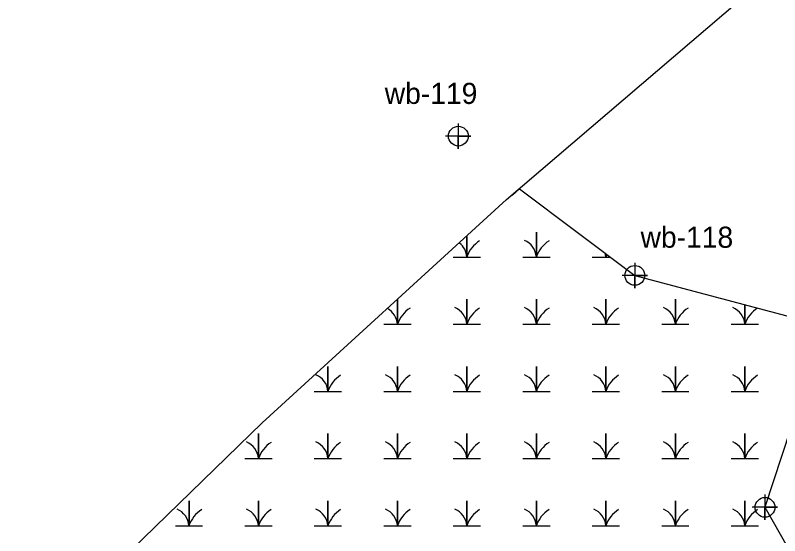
# Model space of a CAD drawing. Extents: x 2379288 to 2381905, y 330670 to 333511.
# Drawn here: x 2380487.2 to 2380668.2, y 332788.3 to 332911.6 of the extents above; entities that cross this region are included whole.
import ezdxf

# ---------------------------------------------------------------- set-up
doc = ezdxf.new("R2010")
doc.units = 0
for name, color, linetype in [('Default', 7, 'Continuous'), ('Exist Environmental Wetland Boundary', 7, 'Continuous'), ('Exist Environmental Wetland Boundary Cogo Number', 7, 'Continuous'), ('Exist Environmental Wetland Boundary Cogo Point CELL', 7, 'Continuous'), ('Exist Hydro Swamp or Marsh', 7, 'Continuous')]:
    doc.layers.add(name, color=color, linetype=linetype)

msp = doc.modelspace()

# ---------------------------------------------------------------- linework, layer by layer
at = {"layer": 'Default'}
msp.add_lwpolyline([(2379288.07, 330873.37), (2380109.3, 332268.58), (2380147.86, 332331.82), (2380190.73, 332397.51), (2380235.65, 332461.81), (2380282.57, 332524.66), (2380331.46, 332586), (2380382.25, 332645.77), (2380434.91, 332703.9), (2380489.37, 332760.35), (2380545.59, 332815.05), (2380603.5, 332867.95), (2380663.06, 332918.99), (2380724.19, 332968.13), (2380786.85, 333015.32), (2380850.96, 333060.51), (2380916.47, 333103.65)], dxfattribs=at)
at = {"layer": 'Exist Environmental Wetland Boundary'}
msp.add_lwpolyline([(2380604.8, 332868.97), (2380606.54, 332870.55), (2380633.85, 332850.01), (2380678.79, 332838.07), (2380664.67, 332795.06), (2380686.7, 332756.16), (2380626.94, 332703.59), (2380578.61, 332658.53)], dxfattribs=at)
at = {"layer": 'Exist Environmental Wetland Boundary Cogo Point CELL'}
for points in [[(2380592.06, 332886), (2380592.06, 332880), (2380592.06, 332883), (2380595.06, 332883), (2380589.06, 332883)], [(2380633.85, 332853.01), (2380633.85, 332847.01), (2380633.85, 332850.01), (2380636.85, 332850.01), (2380630.85, 332850.01)], [(2380664.67, 332798.06), (2380664.67, 332792.06), (2380664.67, 332795.06), (2380667.67, 332795.06), (2380661.67, 332795.06)]]:
    msp.add_lwpolyline(points, dxfattribs=at)
for centre in [(2380592.06, 332883), (2380633.85, 332850.01), (2380664.67, 332795.06)]:
    msp.add_circle(centre, 2.34, dxfattribs=at)
at = {"layer": 'Exist Hydro Swamp or Marsh'}
for points in [[(2380607.32, 332854.36), (2380610.54, 332854.36), (2380610.54, 332860.28), (2380610.54, 332854.36), (2380613.77, 332854.36)], [(2380590.87, 332854.36), (2380594.09, 332854.36), (2380594.09, 332859.24)], [(2380594.09, 332859.24), (2380594.09, 332854.36), (2380597.32, 332854.36)], [(2380623.77, 332854.36), (2380626.99, 332854.36), (2380626.99, 332855.16)], [(2380626.99, 332855.16), (2380626.99, 332854.36), (2380628.06, 332854.36)], [(2380574.42, 332838.45), (2380577.64, 332838.45), (2380577.64, 332844.3)], [(2380577.64, 332844.3), (2380577.64, 332838.45), (2380580.87, 332838.45)], [(2380590.87, 332838.45), (2380594.09, 332838.45), (2380594.09, 332844.36), (2380594.09, 332838.45), (2380597.32, 332838.45)], [(2380607.32, 332838.45), (2380610.54, 332838.45), (2380610.54, 332844.36), (2380610.54, 332838.45), (2380613.77, 332838.45)], [(2380623.77, 332838.45), (2380626.99, 332838.45), (2380626.99, 332844.36), (2380626.99, 332838.45), (2380630.22, 332838.45)], [(2380640.22, 332838.45), (2380643.45, 332838.45), (2380643.45, 332844.36), (2380643.45, 332838.45), (2380646.67, 332838.45)], [(2380656.67, 332838.45), (2380659.9, 332838.45), (2380659.9, 332843.09)], [(2380659.9, 332843.09), (2380659.9, 332838.45), (2380663.12, 332838.45)], [(2380557.96, 332822.53), (2380561.19, 332822.53), (2380561.19, 332828.45), (2380561.19, 332822.53), (2380564.42, 332822.53)], [(2380574.42, 332822.53), (2380577.64, 332822.53), (2380577.64, 332828.45), (2380577.64, 332822.53), (2380580.87, 332822.53)], [(2380590.87, 332822.53), (2380594.09, 332822.53), (2380594.09, 332828.45), (2380594.09, 332822.53), (2380597.32, 332822.53)], [(2380607.32, 332822.53), (2380610.54, 332822.53), (2380610.54, 332828.45), (2380610.54, 332822.53), (2380613.77, 332822.53)], [(2380623.77, 332822.53), (2380626.99, 332822.53), (2380626.99, 332828.45), (2380626.99, 332822.53), (2380630.22, 332822.53)], [(2380640.22, 332822.53), (2380643.45, 332822.53), (2380643.45, 332828.45), (2380643.45, 332822.53), (2380646.67, 332822.53)], [(2380656.67, 332822.53), (2380659.9, 332822.53), (2380659.9, 332828.45), (2380659.9, 332822.53), (2380663.12, 332822.53)], [(2380541.51, 332806.61), (2380544.74, 332806.61), (2380544.74, 332812.53), (2380544.74, 332806.61), (2380547.96, 332806.61)], [(2380557.96, 332806.61), (2380561.19, 332806.61), (2380561.19, 332812.53), (2380561.19, 332806.61), (2380564.42, 332806.61)], [(2380574.42, 332806.61), (2380577.64, 332806.61), (2380577.64, 332812.53), (2380577.64, 332806.61), (2380580.87, 332806.61)], [(2380590.87, 332806.61), (2380594.09, 332806.61), (2380594.09, 332812.53), (2380594.09, 332806.61), (2380597.32, 332806.61)], [(2380607.32, 332806.61), (2380610.54, 332806.61), (2380610.54, 332812.53), (2380610.54, 332806.61), (2380613.77, 332806.61)], [(2380623.77, 332806.61), (2380626.99, 332806.61), (2380626.99, 332812.53), (2380626.99, 332806.61), (2380630.22, 332806.61)], [(2380640.22, 332806.61), (2380643.45, 332806.61), (2380643.45, 332812.53), (2380643.45, 332806.61), (2380646.67, 332806.61)], [(2380656.67, 332806.61), (2380659.9, 332806.61), (2380659.9, 332812.53), (2380659.9, 332806.61), (2380663.12, 332806.61)], [(2380525.06, 332790.69), (2380528.29, 332790.69), (2380528.29, 332796.61), (2380528.29, 332790.69), (2380531.51, 332790.69)], [(2380541.51, 332790.69), (2380544.74, 332790.69), (2380544.74, 332796.61), (2380544.74, 332790.69), (2380547.96, 332790.69)], [(2380557.96, 332790.69), (2380561.19, 332790.69), (2380561.19, 332796.61), (2380561.19, 332790.69), (2380564.42, 332790.69)], [(2380574.42, 332790.69), (2380577.64, 332790.69), (2380577.64, 332796.61), (2380577.64, 332790.69), (2380580.87, 332790.69)], [(2380590.87, 332790.69), (2380594.09, 332790.69), (2380594.09, 332796.61), (2380594.09, 332790.69), (2380597.32, 332790.69)], [(2380607.32, 332790.69), (2380610.54, 332790.69), (2380610.54, 332796.61), (2380610.54, 332790.69), (2380613.77, 332790.69)], [(2380623.77, 332790.69), (2380626.99, 332790.69), (2380626.99, 332796.61), (2380626.99, 332790.69), (2380630.22, 332790.69)], [(2380640.22, 332790.69), (2380643.45, 332790.69), (2380643.45, 332796.61), (2380643.45, 332790.69), (2380646.67, 332790.69)], [(2380656.67, 332790.69), (2380659.9, 332790.69), (2380659.9, 332796.61), (2380659.9, 332790.69), (2380663.12, 332790.69)]]:
    msp.add_lwpolyline(points, dxfattribs=at)
for centre, radius, start, end in [((2380589.49, 332854.03), 4.61, 4.1403, 51.786), ((2380600.93, 332852.09), 7.21, 122.1274, 161.6222), ((2380605.94, 332854.03), 4.61, 4.1403, 67.535), ((2380617.38, 332852.09), 7.21, 122.1274, 161.6222), ((2380622.39, 332854.03), 4.61, 4.1403, 15.7679), ((2380633.84, 332852.09), 7.21, 156.3437, 161.6222), ((2380573.04, 332838.11), 4.61, 4.1403, 61.0144), ((2380584.48, 332836.17), 7.21, 122.1274, 161.6222), ((2380589.49, 332838.11), 4.61, 4.1403, 67.535), ((2380600.93, 332836.17), 7.21, 122.1274, 161.6222), ((2380605.94, 332838.11), 4.61, 4.1403, 67.535), ((2380617.38, 332836.17), 7.21, 122.1274, 161.6222), ((2380622.39, 332838.11), 4.61, 4.1403, 67.535), ((2380633.84, 332836.17), 7.21, 122.1274, 161.6222), ((2380638.85, 332838.11), 4.61, 4.1403, 67.535), ((2380650.29, 332836.17), 7.21, 122.1274, 161.6222), ((2380655.3, 332838.11), 4.61, 4.1403, 67.535), ((2380666.74, 332836.17), 7.21, 122.1274, 161.6222), ((2380556.59, 332822.2), 4.61, 4.1403, 67.535), ((2380568.03, 332820.26), 7.21, 122.1274, 161.6222), ((2380573.04, 332822.2), 4.61, 4.1403, 67.535), ((2380584.48, 332820.26), 7.21, 122.1274, 161.6222), ((2380589.49, 332822.2), 4.61, 4.1403, 67.535), ((2380600.93, 332820.26), 7.21, 122.1274, 161.6222), ((2380605.94, 332822.2), 4.61, 4.1403, 67.535), ((2380617.38, 332820.26), 7.21, 122.1274, 161.6222), ((2380622.39, 332822.2), 4.61, 4.1403, 67.535), ((2380633.84, 332820.26), 7.21, 122.1274, 161.6222), ((2380638.85, 332822.2), 4.61, 4.1403, 67.535), ((2380650.29, 332820.26), 7.21, 122.1274, 161.6222), ((2380655.3, 332822.2), 4.61, 4.1403, 67.535), ((2380666.74, 332820.26), 7.21, 122.1274, 161.6222), ((2380540.14, 332806.28), 4.61, 4.1403, 67.535), ((2380551.58, 332804.34), 7.21, 122.1274, 161.6222), ((2380556.59, 332806.28), 4.61, 4.1403, 67.535), ((2380568.03, 332804.34), 7.21, 122.1274, 161.6222), ((2380573.04, 332806.28), 4.61, 4.1403, 67.535), ((2380584.48, 332804.34), 7.21, 122.1274, 161.6222), ((2380589.49, 332806.28), 4.61, 4.1403, 67.535), ((2380600.93, 332804.34), 7.21, 122.1274, 161.6222), ((2380605.94, 332806.28), 4.61, 4.1403, 67.535), ((2380617.38, 332804.34), 7.21, 122.1274, 161.6222), ((2380622.39, 332806.28), 4.61, 4.1403, 67.535), ((2380633.84, 332804.34), 7.21, 122.1274, 161.6222), ((2380638.85, 332806.28), 4.61, 4.1403, 67.535), ((2380650.29, 332804.34), 7.21, 122.1274, 161.6222), ((2380655.3, 332806.28), 4.61, 4.1403, 67.535), ((2380666.74, 332804.34), 7.21, 122.1274, 161.6222), ((2380523.69, 332790.36), 4.61, 4.1403, 67.535), ((2380535.13, 332788.42), 7.21, 122.1274, 161.6222), ((2380540.14, 332790.36), 4.61, 4.1403, 67.535), ((2380551.58, 332788.42), 7.21, 122.1274, 161.6222), ((2380556.59, 332790.36), 4.61, 4.1403, 67.535), ((2380568.03, 332788.42), 7.21, 122.1274, 161.6222), ((2380573.04, 332790.36), 4.61, 4.1403, 67.535), ((2380584.48, 332788.42), 7.21, 122.1274, 161.6222), ((2380589.49, 332790.36), 4.61, 4.1403, 67.535), ((2380600.93, 332788.42), 7.21, 122.1274, 161.6222), ((2380605.94, 332790.36), 4.61, 4.1403, 67.535), ((2380617.38, 332788.42), 7.21, 122.1274, 161.6222), ((2380622.39, 332790.36), 4.61, 4.1403, 67.535), ((2380633.84, 332788.42), 7.21, 122.1274, 161.6222), ((2380638.85, 332790.36), 4.61, 4.1403, 67.535), ((2380650.29, 332788.42), 7.21, 122.1274, 161.6222), ((2380655.3, 332790.36), 4.61, 4.1403, 67.535), ((2380666.74, 332788.42), 7.21, 122.1274, 161.6222)]:
    msp.add_arc(centre, radius, start, end, dxfattribs=at)

# ---------------------------------------------------------------- texts
at = {"layer": 'Exist Environmental Wetland Boundary Cogo Number'}
for s, p in [('wb-119', (2380574.64, 332890.63)), ('wb-118', (2380635.21, 332856.55))]:
    msp.add_text(s, height=5, dxfattribs=at).set_placement(p)

doc.saveas('drawing.dxf')
